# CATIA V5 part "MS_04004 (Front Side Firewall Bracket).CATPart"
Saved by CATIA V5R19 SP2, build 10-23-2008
Part number: MS_04004 (Front Side Firewall Bracket)
Bounding box of the stored display mesh (mm): x -1135.589 to 0, y -273.336 to 0, z 0 to 136.263
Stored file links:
  D:\EPSA\GIT\ELIZ-2022\01 - Maquette CATIA\MS_Miscellanous_Finish_Assembly\MS_A0400 (Firewall)\MS_04004 (Front Side Firewall Bracket).CATPart
  D:\EPSA\GIT\ELIZ-2022\01 - Maquette CATIA\MS_Miscellanous_Finish_Assembly\MS_A0400 (Firewall)\MS_A0400 (FireWall).CATProduct
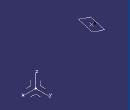
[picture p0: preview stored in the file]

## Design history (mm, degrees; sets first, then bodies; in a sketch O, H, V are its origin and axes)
AxisSystem1: origin (0, 0, 0), X (1, 0, 0), Y (0, 1, 0), Z (0, 0, 1)
Set1
  Point1: type OnCurve, Support DatumCurve1, Length 482.564
  Plane1: type Normal, Curve DatumCurve1, RefPoint Point1
  Sketch1 on Plane1, origin (-966.0201, -277.0747, 406.537), H (0.2757, -0.9612, 0), V (0.3605, 0.1034, 0.927)
    circle A1 centre (-36.6757, -304.8178) radius 14
    point P1 (-36.6757, -304.8178)
    reference projected point E1 (-36.6757, -304.8178) from Point1
    radius A1 = 14
    coincidence: P1 E1
Set2
  DatumCurve1: linked copy from another document
  DatumSurface1: linked copy from another document
Body1 (main body)
  Pad1: profile Sketch1, direction (-0.8911, -0.2556, 0.375), length 60
  Point2: type OnSurface, Support face of Pad1 from Sketch1.A1, Length 16.741, Direction (-0.5584, 0.6698, -0.4894)
  Plane2: type Tangent, Support face of Pad1 from Sketch1.A1, RefPoint Point2
  Point3: type OnSurface, Support Plane2, Length 1172.403, Direction (-0.9729, -0.1784, 0.147)
  Line1: type PtPt, FirstPoint Point3, SecondPoint Point2, End 25
Body2
  Sketch2 on face of DatumSurface1, origin (3.8523, -19.9899, -4.4703), H (-0.9819, -0.1892, 0), V (0.0406, -0.2106, 0.9767)
    reference intersected line E1 (1173.5132, 157.605) -> (1118.1117, 134.5686) from face of Pad1 from Sketch1.A1
    construction line L1 (1148.5377, 147.2199) -> (1158.5201, 123.2126)
    point P3 (1148.5377, 147.2199)
    reference projected point E2 (1147.6799, 149.2828) from Point2
    circle A1 centre (1158.5201, 123.2126) radius 1.7
    arc A2 centre (1158.5201, 123.2126) radius 7 from (1161.2077, 116.7491) to (1164.9836, 125.9002) ccw
    point P5 (1161.2077, 116.7491)
    point P6 (1164.9836, 125.9002)
    line L2 (1164.9836, 125.9002) -> (1155.0012, 149.9075)
    point P7 (1155.0012, 149.9075)
    line L3 (1155.0012, 149.9075) -> (1148.5377, 147.2199)
    point P8 (1148.5377, 147.2199)
    point P9 (1148.5377, 147.2199)
    point P10 (1142.0742, 144.5323)
    line L4 (1142.0742, 144.5323) -> (1148.5377, 147.2199)
    point P11 (1152.0566, 120.525)
    line L5 (1152.0566, 120.525) -> (1142.0742, 144.5323)
    point P12 (1161.2077, 116.7491)
    arc A3 centre (1158.5201, 123.2126) radius 7 from (1161.2077, 116.7491) to (1152.0566, 120.525) cw
    radius A1 = 1.7
    radius A2 = 7
    length L2 = 26
    coincidence: P3 E1, L1 E2, P5 L1, P7 E1, P5 P12, P8 P9
    perpendicularity: L1 E1
    tangency: L2 A2
    parallelism: L3 E1, L2 L1
    symmetry: P8 P9 L1, P7 P10 L1, L3 L4 L1, P6 P11 L1, L2 L5 L1, P5 P12 L1, A2 A3 L1
  Pad2: profile Sketch2, direction (0.1848, -0.9591, -0.2145), length 1.5
  Sketch3 on end face of Pad2, origin (4.1295, -21.4285, -4.792), H (0.9819, 0.1892, 0), V (0.0406, -0.2106, 0.9767)
    intersected line E1 (-1175.9339, 151.7834) -> (-1120.5324, 128.747) from face of Pad1 from Sketch1.A1
    intersected line E2 (-1171.0926, 163.4265) -> (-1115.6911, 140.3901) from face of Pad1 from Sketch1.A1
    point P1 (-1175.9339, 151.7834)
    point P2 (-1120.5324, 128.747)
    line L1 (-1171.0926, 163.4265) -> (-1175.9339, 151.7834)
    point P5 (-1175.9339, 151.7834)
    line L2 (-1115.6911, 140.3901) -> (-1120.5324, 128.747)
    point P6 (-1120.5324, 128.747)
    perpendicularity: L1 E1
    coincidence: P5 E1, P6 E1, P1 P5, P2 P6
    parallelism: L2 L1
  Pocket1: profile Sketch3, direction (-0.1848, 0.9591, 0.2145), up to start face of Pad2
